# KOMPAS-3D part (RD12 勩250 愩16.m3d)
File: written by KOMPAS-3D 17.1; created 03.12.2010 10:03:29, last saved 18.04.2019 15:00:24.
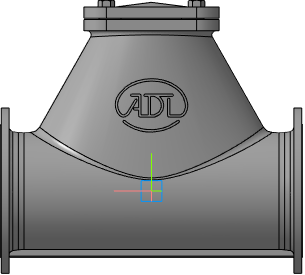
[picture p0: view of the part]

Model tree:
1. Плоскость XY
2. Плоскость ZX
3. Плоскость ZY
4. Ось X
5. Ось Y
6. Ось Z
7. Начало координат
8. Операция без истории:2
